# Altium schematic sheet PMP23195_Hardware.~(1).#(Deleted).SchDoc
size 431 x 279 mm; Date: Not shown in title block; ApprovedBy: Not shown in title block; CheckedBy: Not shown in title block; Author: Not shown in title block; CompanyName: Not shown in title block; Engineer: Not shown in title block; Organization: Not shown in title block; Address1: Not shown in title block; Address2: Not shown in title block; Address3: Not shown in title block; Address4: Not shown in title block; DocumentNumber: 3; Revision: Use project parameter SCH_Rev; SheetNumber: 3; SheetTotal: 6; PageSetup: Record=PageOptions¦CenterHorizontal=True¦CenterVertical=True¦PrintScale=1.00¦XCorrection=1.00¦YCorrection=1.00¦PrintKind=0¦BorderSize=5000000¦LeftOffset=0¦BottomOffset=0¦Orientation=2¦PaperLength=1000¦PaperWidth=1000¦Scale=100¦PaperSource=15¦PrintQuality=600¦MediaType=1¦DitherType=10¦PaperKind=Letter¦PrintScaleMode=1
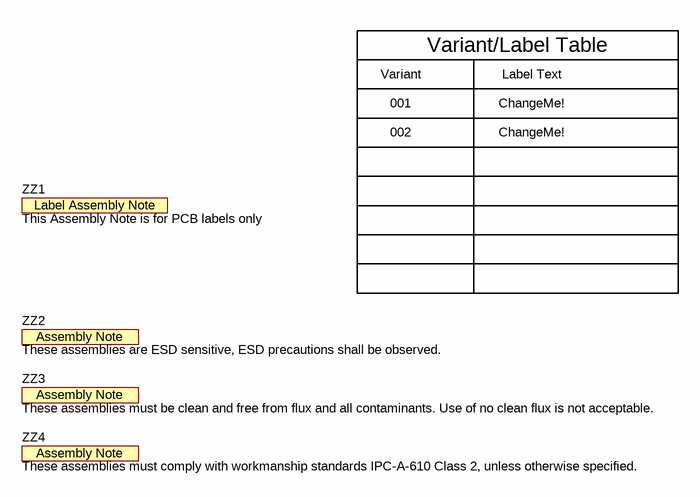
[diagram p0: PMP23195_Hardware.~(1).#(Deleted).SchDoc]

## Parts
ZZ1  This Assembly Note is for PCB labels only  [AssemblyNoteLabel]  (no BOM)
ZZ2  These assemblies are ESD sensitive, ESD precautions shall be observed.  [AssemblyNote]  (no BOM)
ZZ3  These assemblies must be clean and free from flux and all contaminants. Use of no clean flux is not acceptable.  [AssemblyNote]  (no BOM)
ZZ4  These assemblies must comply with workmanship standards IPC-A-610 Class 2, unless otherwise specified.  [AssemblyNote]  (no BOM)

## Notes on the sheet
- Variant
- Variant/Label Table
- Label Text
- 001
- 002
- ChangeMe!

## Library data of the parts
ZZ1 = CMP-0003616-3
ZZ2 = CMP-0077236-1
ZZ3 = CMP-0077237-1
ZZ4 = CMP-0077238-1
